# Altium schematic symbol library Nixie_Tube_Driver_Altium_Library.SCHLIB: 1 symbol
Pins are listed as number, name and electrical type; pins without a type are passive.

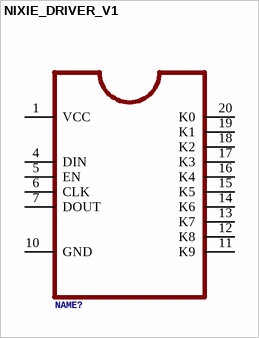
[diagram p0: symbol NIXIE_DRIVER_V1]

## NIXIE_DRIVER_V1
designator NAME?  (value not drawn)
DeviceName: Nixie Driver
footprint NIXIE_DRIVER_V1
pins: 1 VCC (power), 4 DIN, 5 EN, 6 CLK, 7 DOUT, 10 GND (power), 11 K9, 12 K8, 13 K7, 14 K6, 15 K5, 16 K4, 17 K3, 18 K2, 19 K1, 20 K0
